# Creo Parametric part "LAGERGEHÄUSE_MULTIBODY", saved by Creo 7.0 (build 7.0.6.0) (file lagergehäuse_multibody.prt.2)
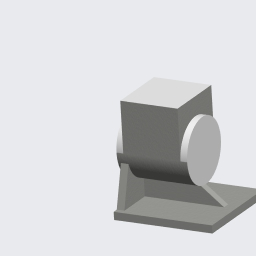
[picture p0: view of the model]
Materials in the file: STAHL

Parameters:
  PTC_MATERIAL_NAME = "STAHL"
  WERKSTOFF = "Stahl"
  ERSTELLER = "ARINDA"
  BENENNUNG = "XXX"
  TEILETYP = "K"
  PTC_MASTER_MATERIAL = "STAHL"
  SCHRAUBEN_GROESSE = "M4x.7"
  METRISCH = "JA"

Other parameters: MASSE, STEIGUNG, BOHR_DURCHM, GEWINDEDURCHMESSER, GEWINDEGÄNGE_PRO_INCH, BOHRER_SPITZENWINKEL, BOHR_TIEFE, GEWINDETIEFE, GEWINDELÄNGE

Created from: LAGERGEHÄUSE.PRT

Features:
  1. coordinate system
  2. datum plane "RECHTS_Y-Z"
  3. datum plane "OBEN_X-Z"
  4. datum plane "VORNE_X-Y"
  5. datum axis
  6. datum axis
  7. datum axis
  8. datum point "PNT0"
  9. protrusion
  10. protrusion
  11. datum plane "DTM1"
  12. protrusion
  13. protrusion
  14. protrusion
  15. protrusion
  16. protrusion
  17. round
  18. round
  19. cut
  20. hole
  21. curve
  22. pattern
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
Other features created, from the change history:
  chamfer "Fase 1"
  patch "Verbundvolumen 1"
  datum point "Bezugspunkt ID 6860"
  datum plane "DTM2"
  datum plane "DTM3"
  planar section "D"
  planar section "E"
  extruded cut "Profil 3"
  feature "Körper Subtrahieren 1"

Other named items: RUNDER_FLANSCH, INNENKONTUR, LAGERSITZ, ECKIGER_FLANSCH, BOHRUNG_OBEN, MUSTER_OBEN, FLANSCH_OBEN, FLANSCH_LINKS, FLANSCH_RE, RIPPE_QUER, FUSS, RIPPE_LÄNGS, MUSTER-FUSSBOHRUNG, AUFDICKUNG_FUß, BOHRUNG_FUß, R6_INNEN, R3, B-B, D-D, E-E, A_X, A_Y, A_Z, CS0

Layers: 01_ACHSEN, 01_ACHSEN_STD, 01_EBENEN, 01_EBENEN_STD, 01_KOORDSYS_STD, 01_KURVEN, 01_PUNKTE, 01_PUNKTE_STD, GEWINDE, SAMMELFLÄCHEN, VOLUMENGEOMETRIE

Notes: M4x.7 | GEWINDEBOHREN | 7.000 |  BOHREN (  | 3.300 | 8.000 |   -(  |  ) BOHRUNG

Surfaces: 19 plane, 1 cylinder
